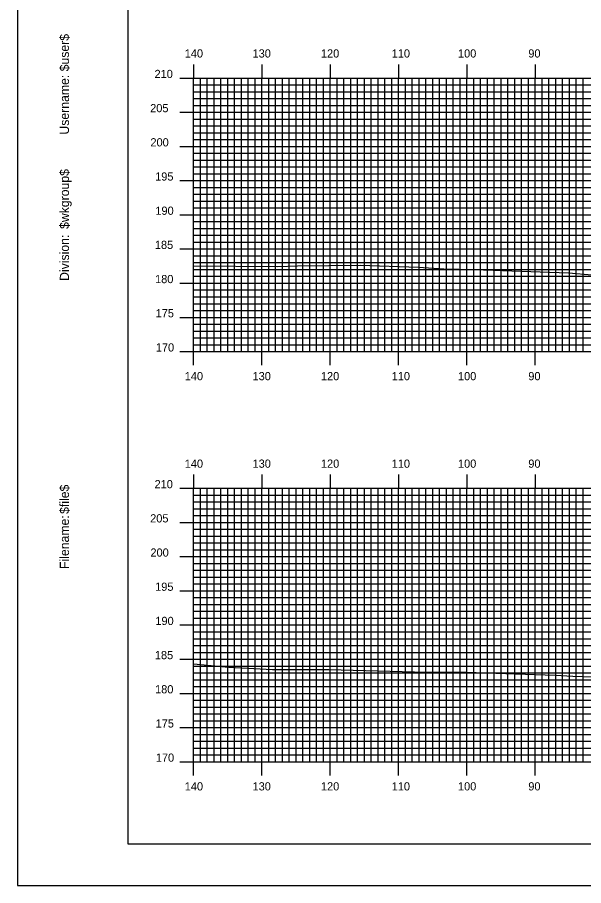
# Model space of a CAD drawing. Extents: x 1809013 to 1809356, y 442591 to 442811.
# Drawn here: x 1809012.5 to 1809095.4, y 442590.5 to 442717.5 of the extents above; entities that cross this region are included whole.
import ezdxf

# ---------------------------------------------------------------- set-up
doc = ezdxf.new("R2010")
doc.units = 0
for name, color, linetype in [('BORDER', 7, 'Continuous'), ('H_V ANNOTATION', 7, 'Continuous'), ('MAJOR', 7, 'Continuous'), ('MINOR', 7, 'Continuous'), ('PLOT BOUNDARY', 7, 'Continuous'), ('S_Roadway_Centerline', 7, 'Continuous')]:
    doc.layers.add(name, color=color, linetype=linetype)

msp = doc.modelspace()

# ---------------------------------------------------------------- linework, layer by layer
at = {"layer": 'BORDER'}
msp.add_lwpolyline([(1809028.72, 442596.67), (1809348.72, 442596.67), (1809348.72, 442806.67), (1809028.72, 442806.67)], close=True, dxfattribs=at)
at = {"layer": 'MAJOR'}
for p, q in [((1809038.32, 442710.67), (1809038.32, 442708.67)), ((1809048.32, 442710.67), (1809048.32, 442708.67)), ((1809058.32, 442710.67), (1809058.32, 442708.67)), ((1809068.32, 442710.67), (1809068.32, 442708.67)), ((1809078.32, 442710.67), (1809078.32, 442708.67)), ((1809088.32, 442710.67), (1809088.32, 442708.67)), ((1809036.32, 442708.67), (1809038.32, 442708.67)), ((1809038.32, 442708.67), (1809318.32, 442708.67)), ((1809038.32, 442668.67), (1809038.32, 442708.67)), ((1809038.32, 442668.67), (1809038.32, 442708.67)), ((1809038.32, 442708.67), (1809318.32, 442708.67)), ((1809048.32, 442668.67), (1809048.32, 442708.67)), ((1809058.32, 442668.67), (1809058.32, 442708.67)), ((1809068.32, 442668.67), (1809068.32, 442708.67)), ((1809078.32, 442668.67), (1809078.32, 442708.67)), ((1809088.32, 442668.67), (1809088.32, 442708.67)), ((1809036.32, 442703.67), (1809038.32, 442703.67)), ((1809038.32, 442703.67), (1809318.32, 442703.67)), ((1809036.32, 442698.67), (1809038.32, 442698.67)), ((1809038.32, 442698.67), (1809318.32, 442698.67)), ((1809036.32, 442693.67), (1809038.32, 442693.67)), ((1809038.32, 442693.67), (1809318.32, 442693.67)), ((1809036.32, 442688.67), (1809038.32, 442688.67)), ((1809038.32, 442688.67), (1809318.32, 442688.67)), ((1809036.32, 442683.67), (1809038.32, 442683.67)), ((1809038.32, 442683.67), (1809318.32, 442683.67)), ((1809036.32, 442678.67), (1809038.32, 442678.67)), ((1809038.32, 442678.67), (1809318.32, 442678.67)), ((1809036.32, 442673.67), (1809038.32, 442673.67)), ((1809038.32, 442673.67), (1809318.32, 442673.67)), ((1809036.32, 442668.67), (1809038.32, 442668.67)), ((1809038.32, 442668.67), (1809318.32, 442668.67)), ((1809038.32, 442668.67), (1809318.32, 442668.67)), ((1809038.32, 442666.66), (1809038.32, 442668.67)), ((1809048.32, 442666.66), (1809048.32, 442668.67)), ((1809058.32, 442666.66), (1809058.32, 442668.67)), ((1809068.32, 442666.66), (1809068.32, 442668.67)), ((1809078.32, 442666.66), (1809078.32, 442668.67)), ((1809088.32, 442666.66), (1809088.32, 442668.67)), ((1809038.32, 442650.67), (1809038.32, 442648.67)), ((1809048.32, 442650.67), (1809048.32, 442648.67)), ((1809058.32, 442650.67), (1809058.32, 442648.67)), ((1809068.32, 442650.67), (1809068.32, 442648.67)), ((1809078.32, 442650.67), (1809078.32, 442648.67)), ((1809088.32, 442650.67), (1809088.32, 442648.67)), ((1809036.32, 442648.67), (1809038.32, 442648.67)), ((1809038.32, 442648.67), (1809318.32, 442648.67)), ((1809038.32, 442608.67), (1809038.32, 442648.67)), ((1809038.32, 442608.67), (1809038.32, 442648.67)), ((1809038.32, 442648.67), (1809318.32, 442648.67)), ((1809048.32, 442608.67), (1809048.32, 442648.67)), ((1809058.32, 442608.67), (1809058.32, 442648.67)), ((1809068.32, 442608.67), (1809068.32, 442648.67)), ((1809078.32, 442608.67), (1809078.32, 442648.67)), ((1809088.32, 442608.67), (1809088.32, 442648.67)), ((1809036.32, 442643.67), (1809038.32, 442643.67)), ((1809038.32, 442643.67), (1809318.32, 442643.67)), ((1809036.32, 442638.67), (1809038.32, 442638.67)), ((1809038.32, 442638.67), (1809318.32, 442638.67)), ((1809036.32, 442633.67), (1809038.32, 442633.67)), ((1809038.32, 442633.67), (1809318.32, 442633.67)), ((1809036.32, 442628.67), (1809038.32, 442628.67)), ((1809038.32, 442628.67), (1809318.32, 442628.67)), ((1809036.32, 442623.67), (1809038.32, 442623.67)), ((1809038.32, 442623.67), (1809318.32, 442623.67)), ((1809036.32, 442618.67), (1809038.32, 442618.67)), ((1809038.32, 442618.67), (1809318.32, 442618.67)), ((1809036.32, 442613.67), (1809038.32, 442613.67)), ((1809038.32, 442613.67), (1809318.32, 442613.67)), ((1809036.32, 442608.67), (1809038.32, 442608.67)), ((1809038.32, 442608.67), (1809318.32, 442608.67)), ((1809038.32, 442608.67), (1809318.32, 442608.67)), ((1809038.32, 442606.66), (1809038.32, 442608.67)), ((1809048.32, 442606.66), (1809048.32, 442608.67)), ((1809058.32, 442606.66), (1809058.32, 442608.67)), ((1809068.32, 442606.66), (1809068.32, 442608.67)), ((1809078.32, 442606.66), (1809078.32, 442608.67)), ((1809088.32, 442606.66), (1809088.32, 442608.67))]:
    msp.add_line(p, q, dxfattribs=at)
at = {"layer": 'MINOR'}
for p, q in [((1809039.32, 442668.67), (1809039.32, 442708.67)), ((1809040.32, 442668.67), (1809040.32, 442708.67)), ((1809041.32, 442668.67), (1809041.32, 442708.67)), ((1809042.32, 442668.67), (1809042.32, 442708.67)), ((1809043.32, 442668.67), (1809043.32, 442708.67)), ((1809044.32, 442668.67), (1809044.32, 442708.67)), ((1809045.32, 442668.67), (1809045.32, 442708.67)), ((1809046.32, 442668.67), (1809046.32, 442708.67)), ((1809047.32, 442668.67), (1809047.32, 442708.67)), ((1809049.32, 442668.67), (1809049.32, 442708.67)), ((1809050.32, 442668.67), (1809050.32, 442708.67)), ((1809051.32, 442668.67), (1809051.32, 442708.67)), ((1809052.32, 442668.67), (1809052.32, 442708.67)), ((1809053.32, 442668.67), (1809053.32, 442708.67)), ((1809054.32, 442668.67), (1809054.32, 442708.67)), ((1809055.32, 442668.67), (1809055.32, 442708.67)), ((1809056.32, 442668.67), (1809056.32, 442708.67)), ((1809057.32, 442668.67), (1809057.32, 442708.67)), ((1809059.32, 442668.67), (1809059.32, 442708.67)), ((1809060.32, 442668.67), (1809060.32, 442708.67)), ((1809061.32, 442668.67), (1809061.32, 442708.67)), ((1809062.32, 442668.67), (1809062.32, 442708.67)), ((1809063.32, 442668.67), (1809063.32, 442708.67)), ((1809064.32, 442668.67), (1809064.32, 442708.67)), ((1809065.32, 442668.67), (1809065.32, 442708.67)), ((1809066.32, 442668.67), (1809066.32, 442708.67)), ((1809067.32, 442668.67), (1809067.32, 442708.67)), ((1809069.32, 442668.67), (1809069.32, 442708.67)), ((1809070.32, 442668.67), (1809070.32, 442708.67)), ((1809071.32, 442668.67), (1809071.32, 442708.67)), ((1809072.32, 442668.67), (1809072.32, 442708.67)), ((1809073.32, 442668.67), (1809073.32, 442708.67)), ((1809074.32, 442668.67), (1809074.32, 442708.67)), ((1809075.32, 442668.67), (1809075.32, 442708.67)), ((1809076.32, 442668.67), (1809076.32, 442708.67)), ((1809077.32, 442668.67), (1809077.32, 442708.67)), ((1809079.32, 442668.67), (1809079.32, 442708.67)), ((1809080.32, 442668.67), (1809080.32, 442708.67)), ((1809081.32, 442668.67), (1809081.32, 442708.67)), ((1809082.32, 442668.67), (1809082.32, 442708.67)), ((1809083.32, 442668.67), (1809083.32, 442708.67)), ((1809084.32, 442668.67), (1809084.32, 442708.67)), ((1809085.32, 442668.67), (1809085.32, 442708.67)), ((1809086.32, 442668.67), (1809086.32, 442708.67)), ((1809087.32, 442668.67), (1809087.32, 442708.67)), ((1809089.32, 442668.67), (1809089.32, 442708.67)), ((1809090.32, 442668.67), (1809090.32, 442708.67)), ((1809091.32, 442668.67), (1809091.32, 442708.67)), ((1809092.32, 442668.67), (1809092.32, 442708.67)), ((1809093.32, 442668.67), (1809093.32, 442708.67)), ((1809094.32, 442668.67), (1809094.32, 442708.67)), ((1809095.32, 442668.67), (1809095.32, 442708.67)), ((1809038.32, 442707.67), (1809318.32, 442707.67)), ((1809038.32, 442707.67), (1809040.33, 442707.67)), ((1809038.32, 442706.67), (1809318.32, 442706.67)), ((1809038.32, 442706.67), (1809040.33, 442706.67)), ((1809038.32, 442705.67), (1809318.32, 442705.67)), ((1809038.32, 442705.67), (1809040.33, 442705.67)), ((1809038.32, 442704.67), (1809318.32, 442704.67)), ((1809038.32, 442704.67), (1809040.33, 442704.67)), ((1809038.32, 442702.67), (1809318.32, 442702.67)), ((1809038.32, 442702.67), (1809040.33, 442702.67)), ((1809038.32, 442701.67), (1809318.32, 442701.67)), ((1809038.32, 442701.67), (1809040.33, 442701.67)), ((1809038.32, 442700.67), (1809318.32, 442700.67)), ((1809038.32, 442700.67), (1809040.33, 442700.67)), ((1809038.32, 442699.67), (1809318.32, 442699.67)), ((1809038.32, 442699.67), (1809040.33, 442699.67)), ((1809038.32, 442697.67), (1809318.32, 442697.67)), ((1809038.32, 442697.67), (1809040.33, 442697.67)), ((1809038.32, 442696.67), (1809318.32, 442696.67)), ((1809038.32, 442696.67), (1809040.33, 442696.67)), ((1809038.32, 442695.67), (1809318.32, 442695.67)), ((1809038.32, 442695.67), (1809040.33, 442695.67)), ((1809038.32, 442694.67), (1809318.32, 442694.67)), ((1809038.32, 442694.67), (1809040.33, 442694.67)), ((1809038.32, 442692.67), (1809318.32, 442692.67)), ((1809038.32, 442692.67), (1809040.33, 442692.67)), ((1809038.32, 442691.67), (1809318.32, 442691.67)), ((1809038.32, 442691.67), (1809040.33, 442691.67)), ((1809038.32, 442690.67), (1809318.32, 442690.67)), ((1809038.32, 442690.67), (1809040.33, 442690.67)), ((1809038.32, 442689.67), (1809318.32, 442689.67)), ((1809038.32, 442689.67), (1809040.33, 442689.67)), ((1809038.32, 442687.67), (1809318.32, 442687.67)), ((1809038.32, 442687.67), (1809040.33, 442687.67)), ((1809038.32, 442686.67), (1809318.32, 442686.67)), ((1809038.32, 442686.67), (1809040.33, 442686.67)), ((1809038.32, 442685.67), (1809318.32, 442685.67)), ((1809038.32, 442685.67), (1809040.33, 442685.67)), ((1809038.32, 442684.67), (1809318.32, 442684.67)), ((1809038.32, 442684.67), (1809040.33, 442684.67)), ((1809038.32, 442682.67), (1809318.32, 442682.67)), ((1809038.32, 442682.67), (1809040.33, 442682.67)), ((1809038.32, 442681.67), (1809318.32, 442681.67)), ((1809038.32, 442681.67), (1809040.33, 442681.67)), ((1809038.32, 442680.67), (1809318.32, 442680.67)), ((1809038.32, 442680.67), (1809040.33, 442680.67)), ((1809038.32, 442679.67), (1809318.32, 442679.67)), ((1809038.32, 442679.67), (1809040.33, 442679.67)), ((1809038.32, 442677.67), (1809318.32, 442677.67)), ((1809038.32, 442677.67), (1809040.33, 442677.67)), ((1809038.32, 442676.67), (1809318.32, 442676.67)), ((1809038.32, 442676.67), (1809040.33, 442676.67)), ((1809038.32, 442675.67), (1809318.32, 442675.67)), ((1809038.32, 442675.67), (1809040.33, 442675.67)), ((1809038.32, 442674.67), (1809318.32, 442674.67)), ((1809038.32, 442674.67), (1809040.33, 442674.67)), ((1809038.32, 442672.67), (1809318.32, 442672.67)), ((1809038.32, 442672.67), (1809040.33, 442672.67)), ((1809038.32, 442671.67), (1809318.32, 442671.67)), ((1809038.32, 442671.67), (1809040.33, 442671.67)), ((1809038.32, 442670.67), (1809318.32, 442670.67)), ((1809038.32, 442670.67), (1809040.33, 442670.67)), ((1809038.32, 442669.67), (1809318.32, 442669.67)), ((1809038.32, 442669.67), (1809040.33, 442669.67)), ((1809039.32, 442608.67), (1809039.32, 442648.67)), ((1809040.32, 442608.67), (1809040.32, 442648.67)), ((1809041.32, 442608.67), (1809041.32, 442648.67)), ((1809042.32, 442608.67), (1809042.32, 442648.67)), ((1809043.32, 442608.67), (1809043.32, 442648.67)), ((1809044.32, 442608.67), (1809044.32, 442648.67)), ((1809045.32, 442608.67), (1809045.32, 442648.67)), ((1809046.32, 442608.67), (1809046.32, 442648.67)), ((1809047.32, 442608.67), (1809047.32, 442648.67)), ((1809049.32, 442608.67), (1809049.32, 442648.67)), ((1809050.32, 442608.67), (1809050.32, 442648.67)), ((1809051.32, 442608.67), (1809051.32, 442648.67)), ((1809052.32, 442608.67), (1809052.32, 442648.67)), ((1809053.32, 442608.67), (1809053.32, 442648.67)), ((1809054.32, 442608.67), (1809054.32, 442648.67)), ((1809055.32, 442608.67), (1809055.32, 442648.67)), ((1809056.32, 442608.67), (1809056.32, 442648.67)), ((1809057.32, 442608.67), (1809057.32, 442648.67)), ((1809059.32, 442608.67), (1809059.32, 442648.67)), ((1809060.32, 442608.67), (1809060.32, 442648.67)), ((1809061.32, 442608.67), (1809061.32, 442648.67)), ((1809062.32, 442608.67), (1809062.32, 442648.67)), ((1809063.32, 442608.67), (1809063.32, 442648.67)), ((1809064.32, 442608.67), (1809064.32, 442648.67)), ((1809065.32, 442608.67), (1809065.32, 442648.67)), ((1809066.32, 442608.67), (1809066.32, 442648.67)), ((1809067.32, 442608.67), (1809067.32, 442648.67)), ((1809069.32, 442608.67), (1809069.32, 442648.67)), ((1809070.32, 442608.67), (1809070.32, 442648.67)), ((1809071.32, 442608.67), (1809071.32, 442648.67)), ((1809072.32, 442608.67), (1809072.32, 442648.67)), ((1809073.32, 442608.67), (1809073.32, 442648.67)), ((1809074.32, 442608.67), (1809074.32, 442648.67)), ((1809075.32, 442608.67), (1809075.32, 442648.67)), ((1809076.32, 442608.67), (1809076.32, 442648.67)), ((1809077.32, 442608.67), (1809077.32, 442648.67)), ((1809079.32, 442608.67), (1809079.32, 442648.67)), ((1809080.32, 442608.67), (1809080.32, 442648.67)), ((1809081.32, 442608.67), (1809081.32, 442648.67)), ((1809082.32, 442608.67), (1809082.32, 442648.67)), ((1809083.32, 442608.67), (1809083.32, 442648.67)), ((1809084.32, 442608.67), (1809084.32, 442648.67)), ((1809085.32, 442608.67), (1809085.32, 442648.67)), ((1809086.32, 442608.67), (1809086.32, 442648.67)), ((1809087.32, 442608.67), (1809087.32, 442648.67)), ((1809089.32, 442608.67), (1809089.32, 442648.67)), ((1809090.32, 442608.67), (1809090.32, 442648.67)), ((1809091.32, 442608.67), (1809091.32, 442648.67)), ((1809092.32, 442608.67), (1809092.32, 442648.67)), ((1809093.32, 442608.67), (1809093.32, 442648.67)), ((1809094.32, 442608.67), (1809094.32, 442648.67)), ((1809095.32, 442608.67), (1809095.32, 442648.67)), ((1809038.32, 442647.67), (1809318.32, 442647.67)), ((1809038.32, 442647.67), (1809040.33, 442647.67)), ((1809038.32, 442646.67), (1809318.32, 442646.67)), ((1809038.32, 442646.67), (1809040.33, 442646.67)), ((1809038.32, 442645.67), (1809318.32, 442645.67)), ((1809038.32, 442645.67), (1809040.33, 442645.67)), ((1809038.32, 442644.67), (1809318.32, 442644.67)), ((1809038.32, 442644.67), (1809040.33, 442644.67)), ((1809038.32, 442642.67), (1809318.32, 442642.67)), ((1809038.32, 442642.67), (1809040.33, 442642.67)), ((1809038.32, 442641.67), (1809318.32, 442641.67)), ((1809038.32, 442641.67), (1809040.33, 442641.67)), ((1809038.32, 442640.67), (1809318.32, 442640.67)), ((1809038.32, 442640.67), (1809040.33, 442640.67)), ((1809038.32, 442639.67), (1809318.32, 442639.67)), ((1809038.32, 442639.67), (1809040.33, 442639.67)), ((1809038.32, 442637.67), (1809318.32, 442637.67)), ((1809038.32, 442637.67), (1809040.33, 442637.67)), ((1809038.32, 442636.67), (1809318.32, 442636.67)), ((1809038.32, 442636.67), (1809040.33, 442636.67)), ((1809038.32, 442635.67), (1809318.32, 442635.67)), ((1809038.32, 442635.67), (1809040.33, 442635.67)), ((1809038.32, 442634.67), (1809318.32, 442634.67)), ((1809038.32, 442634.67), (1809040.33, 442634.67)), ((1809038.32, 442632.67), (1809318.32, 442632.67)), ((1809038.32, 442632.67), (1809040.33, 442632.67)), ((1809038.32, 442631.67), (1809318.32, 442631.67)), ((1809038.32, 442631.67), (1809040.33, 442631.67)), ((1809038.32, 442630.67), (1809318.32, 442630.67)), ((1809038.32, 442630.67), (1809040.33, 442630.67)), ((1809038.32, 442629.67), (1809318.32, 442629.67)), ((1809038.32, 442629.67), (1809040.33, 442629.67)), ((1809038.32, 442627.67), (1809318.32, 442627.67)), ((1809038.32, 442627.67), (1809040.33, 442627.67)), ((1809038.32, 442626.67), (1809318.32, 442626.67)), ((1809038.32, 442626.67), (1809040.33, 442626.67)), ((1809038.32, 442625.67), (1809318.32, 442625.67)), ((1809038.32, 442625.67), (1809040.33, 442625.67)), ((1809038.32, 442624.67), (1809318.32, 442624.67)), ((1809038.32, 442624.67), (1809040.33, 442624.67)), ((1809038.32, 442622.67), (1809318.32, 442622.67)), ((1809038.32, 442622.67), (1809040.33, 442622.67)), ((1809038.32, 442621.67), (1809318.32, 442621.67)), ((1809038.32, 442621.67), (1809040.33, 442621.67)), ((1809038.32, 442620.67), (1809318.32, 442620.67)), ((1809038.32, 442620.67), (1809040.33, 442620.67)), ((1809038.32, 442619.67), (1809318.32, 442619.67)), ((1809038.32, 442619.67), (1809040.33, 442619.67)), ((1809038.32, 442617.67), (1809318.32, 442617.67)), ((1809038.32, 442617.67), (1809040.33, 442617.67)), ((1809038.32, 442616.67), (1809318.32, 442616.67)), ((1809038.32, 442616.67), (1809040.33, 442616.67)), ((1809038.32, 442615.67), (1809318.32, 442615.67)), ((1809038.32, 442615.67), (1809040.33, 442615.67)), ((1809038.32, 442614.67), (1809318.32, 442614.67)), ((1809038.32, 442614.67), (1809040.33, 442614.67)), ((1809038.32, 442612.67), (1809318.32, 442612.67)), ((1809038.32, 442612.67), (1809040.33, 442612.67)), ((1809038.32, 442611.67), (1809318.32, 442611.67)), ((1809038.32, 442611.67), (1809040.33, 442611.67)), ((1809038.32, 442610.67), (1809318.32, 442610.67)), ((1809038.32, 442610.67), (1809040.33, 442610.67)), ((1809038.32, 442609.67), (1809318.32, 442609.67)), ((1809038.32, 442609.67), (1809040.33, 442609.67))]:
    msp.add_line(p, q, dxfattribs=at)
at = {"layer": 'PLOT BOUNDARY'}
msp.add_lwpolyline([(1809012.54, 442590.55), (1809352.54, 442590.55), (1809352.54, 442810.55), (1809012.54, 442810.55)], close=True, dxfattribs=at)
at = {"layer": 'S_Roadway_Centerline'}
for points in [[(1809038.32, 442681.19), (1809050.67, 442681.12), (1809053.52, 442681.18), (1809062.72, 442681.32), (1809071.22, 442681), (1809074.92, 442680.75), (1809079.4, 442680.68), (1809093.17, 442680.19), (1809096.65, 442679.9)], [(1809038.32, 442622.97), (1809043.49, 442622.48), (1809049.88, 442622.16), (1809058.12, 442622.14), (1809070.64, 442621.8), (1809078.23, 442621.76), (1809091.25, 442621.32), (1809093.8, 442621.19), (1809096.91, 442621.11), (1809112.84, 442620.5), (1809121.56, 442620.32), (1809134.65, 442620.35), (1809146.51, 442620.13), (1809154.66, 442620.03), (1809163.34, 442619.91), (1809185.99, 442619.22), (1809188.55, 442619.14), (1809191.72, 442619.08), (1809193.97, 442619.02), (1809218.3, 442618.76)]]:
    msp.add_lwpolyline(points, dxfattribs=at)

# ---------------------------------------------------------------- texts
at = {"layer": 'BORDER'}
for s, p in [('$user$', (1809020.09, 442709.65)), ('Username:', (1809020.09, 442700.4)), ('$wkgroup$', (1809020.09, 442686.6)), ('Division:', (1809020.09, 442679)), ('$file$', (1809020.09, 442644.92)), ('Filename:', (1809020.09, 442636.86))]:
    msp.add_text(s, height=1.339, rotation=90, dxfattribs=at).set_placement(p)
at = {"layer": 'H_V ANNOTATION'}
for s, p in [('140', (1809037.03, 442711.67)), ('130', (1809046.95, 442711.67)), ('120', (1809056.96, 442711.67)), ('110', (1809067.31, 442711.67)), ('100', (1809077.01, 442711.67)), ('90', (1809087.3, 442711.67)), ('210', (1809032.61, 442708.67)), ('205', (1809031.97, 442703.67)), ('200', (1809032.01, 442698.67)), ('195', (1809032.7, 442693.67)), ('190', (1809032.73, 442688.67)), ('185', (1809032.66, 442683.67)), ('180', (1809032.69, 442678.67)), ('175', (1809032.77, 442673.67)), ('170', (1809032.8, 442668.67)), ('140', (1809037.03, 442664.47)), ('130', (1809046.95, 442664.47)), ('120', (1809056.96, 442664.47)), ('110', (1809067.31, 442664.47)), ('100', (1809077.01, 442664.47)), ('90', (1809087.3, 442664.47)), ('140', (1809037.03, 442651.67)), ('130', (1809046.95, 442651.67)), ('120', (1809056.96, 442651.67)), ('110', (1809067.31, 442651.67)), ('100', (1809077.01, 442651.67)), ('90', (1809087.3, 442651.67)), ('210', (1809032.61, 442648.67)), ('205', (1809031.97, 442643.67)), ('200', (1809032.01, 442638.67)), ('195', (1809032.7, 442633.67)), ('190', (1809032.73, 442628.67)), ('185', (1809032.66, 442623.67)), ('180', (1809032.69, 442618.67)), ('175', (1809032.77, 442613.67)), ('170', (1809032.8, 442608.67)), ('140', (1809037.03, 442604.47)), ('130', (1809046.95, 442604.47)), ('120', (1809056.96, 442604.47)), ('110', (1809067.31, 442604.47)), ('100', (1809077.01, 442604.47)), ('90', (1809087.3, 442604.47))]:
    msp.add_text(s, height=1.2, dxfattribs=at).set_placement(p)
at = {"layer": 'MAJOR'}
for p in [(1809038.32, 442668.67), (1809038.32, 442608.67)]:
    msp.add_text('-', height=0.012, dxfattribs=at).set_placement(p)

doc.saveas('drawing.dxf')
